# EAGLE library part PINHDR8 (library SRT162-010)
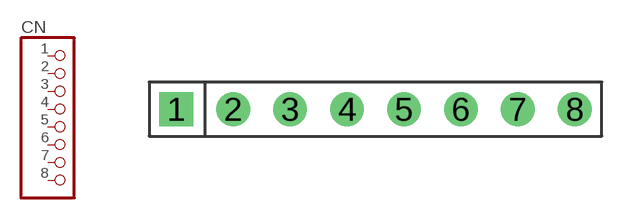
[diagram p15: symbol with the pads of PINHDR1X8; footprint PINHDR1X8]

Designator prefix CN

## PINHDR8  [PINHDR1X8]
1  1  pas
2  2  pas
3  3  pas
4  4  pas
5  5  pas
6  6  pas
7  7  pas
8  8  pas

## Footprint PINHDR1X8 (pad centres in mm)
drill 1 square: 1 -8.89,0
drill 1 round: 2 -6.35,0; 3 -3.81,0; 4 -1.27,0; 5 1.27,0; 6 3.81,0; 7 6.35,0; 8 8.89,0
